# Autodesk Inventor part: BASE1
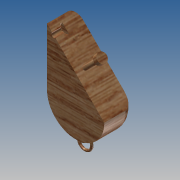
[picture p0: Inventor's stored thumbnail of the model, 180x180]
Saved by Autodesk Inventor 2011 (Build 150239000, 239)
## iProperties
Created: 2011-01
Part Number: BASE1
Document SubType Name: Modeling
Designer: Microsoft
Density: 1 g/cm^3
Author: Microsoft
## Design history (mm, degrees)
sketch "Sketch1"
  geometry: L1 (9.525, 0)-(9.525, 19.05); L2 (-9.525, 19.05)-(-9.525, 0); L3 (-9.525, 19.05)-(9.525, 0); A1 r 9.525 centre (0, 0) between (-9.525, 0) and (9.525, 0); A2 r 9.525 centre (0, 19.05) between (9.525, 19.05) and (-9.525, 19.05); 1 further point
  constraints: 6 end point, 4 point on circle, 3 tangent, 2 centre point, 1 coincident, 1 vertical alignment
  dimensions: "d3" = 9.525 radius of A2; "d4" = 9.525 radius of A1; "d5" = 19.05 distance of L1.start L1.end; "d6" = 19.05 distance of point (0, 0) A2.centre
extrude "Extrusion1" new body sketch "Sketch1" distance "d7" = 12.7; taper "d8" = 0 deg
sketch "Sketch2"
  geometry: L1 (13.47, 0)-(13.47, 12.7) reference; L2 (0, 0)-(26.941, 0) reference; C1 r 0.794 at (13.47, 6.35); 1 further point
  constraints: 1 centre point, 1 midpoint
  dimensions: "d31" = 1.5875 diameter of C1; "d32" = 6.35 distance from line of L2 C1.centre
extrude "Extrusion2" join sketch "Sketch2" distance "d10" = 6.35; taper "d11" = 0 deg
sketch "Sketch3"
  geometry: C1 r 1.587 at (0, -3.175); C2 r 0.794 at (0, -3.175) reference; 1 further point
  constraints: 1 centre point, 1 concentric
  dimensions: "d12" = 3.175 diameter of C1
extrude "Extrusion3" join sketch "Sketch3" distance "d13" = 1.5875; taper "d14" = 0 deg
workplane "Work Plane1"
sketch "Sketch5"
  geometry: L1 (-9.525, 19.05)-(-8.622, 19.953); L2 (9.525, 0)-(-9.525, 19.05) reference; C1 r 0.794 at (-7.28, 16.805); 1 further point
  constraints: 2 end point, 1 centre point, 1 perpendicular, 1 point on line
  dimensions: "d21" = 1.5875 diameter of C1; "d22" = 3.175 distance from line of L1 C1.centre
extrude "Extrusion4" cut sketch "Sketch5" distance "d23" = 3.175; taper "d24" = 0 deg
sketch "Sketch6"
  geometry: C1 r 1.588 at (-7.28, -16.805); A1 r 0.794 centre (-7.28, -16.805) between (-6.719, -16.244) and (-7.841, -17.366) reference; 1 further point
  constraints: 1 centre point, 1 coincident
  dimensions: "d25" = 3.175 diameter of C1
extrude "Extrusion5" cut sketch "Sketch6" distance "d26" = 1.5875; taper "d27" = 0 deg
fillet "Fillet1" dims "d30" = 2.54
sketch "Sketch8"
  geometry: L1 (-9.525, 19.05)-(9.525, 0) reference; L2 (-9.525, 0)-(-9.525, 19.05) reference; A1 r 9.525 centre (0, 0) between (-9.525, 0) and (9.525, 0) reference
extrude "Extrusion7" cut sketch "Sketch8" distance "d33" = 3.175; taper "d34" = 0 deg
sketch "Sketch9"
  geometry: L1 (7.841, -17.366)-(6.719, -16.244) reference; C1 r 1.588 at (7.28, -16.805); A1 r 0.794 centre (7.28, -16.805) between (6.719, -16.244) and (7.841, -17.366) reference; 1 further point
  constraints: 1 centre point, 1 coincident
  dimensions: "d37" = 3.175 diameter of C1
extrude "Extrusion8" cut sketch "Sketch9" distance "d35" = 0.79375; taper "d36" = 0 deg
workplane "Work Plane2"
workplane "Work Plane4"
workplane "Work Plane5"
sketch "Sketch14"
  geometry: L1 (1.588, -7.864)-(-1.587, -7.864); L2 (-1.587, -7.864)-(-1.587, -11.113); L3 (-1.587, -11.113)-(1.588, -11.113); L4 (1.588, -11.113)-(1.588, -7.864); L5 (0, -7.864)-(0, -11.113); 2 further points
  constraints: 10 end point, 2 midpoint, 2 parallel, 1 horizontal, 1 perpendicular
  dimensions: "d53" = 1.5875 distance from line of L4 point (0, 0); "d54" = 1.5875 distance from line of point (0, 0) L2; "d55" = 11.1125 distance from line of point (0, 0) L3
revolve "Revolution4" sketch "Sketch14" stored, may be unused: angle "d56" = 90 deg
sketch "Sketch15"
  geometry: L1 (0, -7.937)-(0, -11.112); C1 r 0.397 at (-2.181, -9.525); A1 r 1.588 centre (0, -9.525) between (0, -7.937) and (0, -11.112); 1 further point
  constraints: 2 centre point, 2 end point, 2 point on circle, 1 vertical
  dimensions: "d57" = 0.79375 diameter of C1; "d58" = 6.35 distance of point (0, -15.875) A1.centre; "d59" = 6.35 vertical distance of point (0, -15.875) C1.centre
revolve "Revolution5" sketch "Sketch15" stored, may be unused: angle "d60" = 90 deg
body "Solid1"
other parameters: "d17" = -6.35, "d40" = 6.35, "d52" = -6.35
